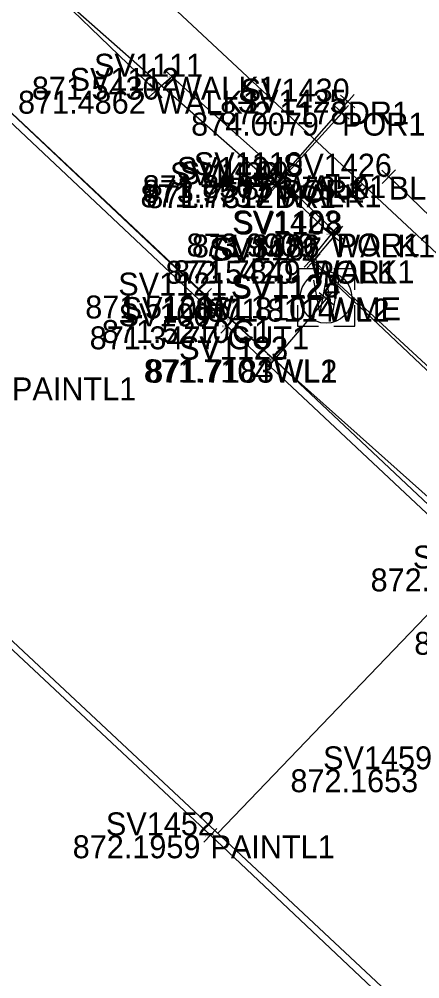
# Model space of a CAD drawing. Extents: x 1469677 to 1493262, y 375219 to 389293.
# Drawn here: x 1480076.7 to 1480097.7, y 379497.6 to 379547.9 of the extents above; entities that cross this region are included whole.
import ezdxf

# ---------------------------------------------------------------- set-up
doc = ezdxf.new("R2010")
doc.units = 0
for name, color, linetype in [('Border', 7, 'Continuous'), ('Building', 7, 'Continuous'), ('DR_X_Drive_Pipe', 7, 'Continuous'), ('DV_X_Lot_Line', 7, 'Continuous'), ('DV_X_Text', 7, 'Continuous'), ('GK_Visualization', 7, 'Continuous'), ('PNTELEV', 7, 'Continuous'), ('PNTNO', 7, 'Continuous'), ('RD_P_Text', 7, 'Continuous'), ('RW_P_Esmt_SW', 7, 'Continuous'), ('SV_X_Mon_Cells_Found', 7, 'Continuous'), ('SV_X_Text_Elevation', 7, 'Continuous'), ('Text Border', 7, 'Continuous'), ('UT_X_Water', 7, 'Continuous')]:
    doc.layers.add(name, color=color, linetype=linetype)

msp = doc.modelspace()

# ---------------------------------------------------------------- linework, layer by layer
at = {"layer": 'Border'}
msp.add_lwpolyline([(1480114.175, 379522.123), (1480096.037, 379539.648)], dxfattribs=at)
at = {"layer": 'Building'}
msp.add_lwpolyline([(1480030.312, 379558.368), (1480048.994, 379540.544), (1480068.184, 379522.458), (1480086.697, 379505.162), (1480104.247, 379488.61), (1480122.276, 379471.896), (1480139.96, 379455.601)], dxfattribs=at)
at = {"layer": 'DR_X_Drive_Pipe'}
for points in [[(1480049.152, 379568.017), (1480068.611, 379550.193), (1480086.403, 379533.424), (1480090.024, 379530.079), (1480102.295, 379519.134), (1480111.734, 379511.473), (1480120.332, 379509.136), (1480127.535, 379501.668), (1480127.911, 379496.395), (1480140.166, 379484.084), (1480149.088, 379474.708), (1480164.726, 379459.482), (1480172.622, 379452.503), (1480197.813, 379429.111)], [(1480090.047, 379530.062), (1480092.778, 379533.259)]]:
    msp.add_lwpolyline(points, dxfattribs=at)
at = {"layer": 'DV_X_Lot_Line'}
msp.add_lwpolyline([(1480215.341, 379421.047), (1480197.466, 379437.463), (1480177.803, 379455.97), (1480154.79, 379476.967), (1480132.747, 379497.48), (1480113.376, 379516.728), (1480110.754, 379519.04), (1480109.877, 379518.336), (1480091.944, 379535.267), (1480093.027, 379536.619), (1480090.219, 379539.243), (1480090.463, 379539.725), (1480084.681, 379544.882), (1480083.843, 379544.144), (1480066.818, 379560.524), (1480045.662, 379580.046)], dxfattribs=at)
at = {"layer": 'PNTELEV'}
for p, q in [((1480085.054, 379544.549), (1480084.308, 379545.215)), ((1480084.348, 379544.509), (1480085.014, 379545.255)), ((1480084.681, 379544.882), (1480084.681, 379544.882)), ((1480084.218, 379544.474), (1480083.467, 379543.814)), ((1480084.173, 379543.769), (1480083.512, 379544.519)), ((1480083.843, 379544.144), (1480083.843, 379544.144)), ((1480093.514, 379543.909), (1480094.267, 379543.25)), ((1480093.561, 379543.203), (1480094.22, 379543.956)), ((1480093.256, 379542.625), (1480093.928, 379543.365)), ((1480093.891, 379543.58), (1480093.891, 379543.58)), ((1480093.222, 379543.332), (1480093.962, 379542.659)), ((1480093.592, 379542.995), (1480093.592, 379542.995)), ((1480090.016, 379539.951), (1480090.909, 379539.5)), ((1480090.756, 379539.134), (1480090.036, 379539.829)), ((1480090.049, 379539.122), (1480090.743, 379539.841)), ((1480090.237, 379539.279), (1480090.688, 379540.172)), ((1480096.397, 379539.3), (1480095.678, 379539.995)), ((1480095.69, 379539.288), (1480096.385, 379540.007)), ((1480089.684, 379539.531), (1480090.433, 379538.869)), ((1480090.389, 379539.575), (1480089.728, 379538.825)), ((1480090.584, 379538.902), (1480089.854, 379539.585)), ((1480089.878, 379538.878), (1480090.56, 379539.608)), ((1480090.396, 379539.481), (1480090.396, 379539.481)), ((1480090.463, 379539.725), (1480090.463, 379539.725)), ((1480096.037, 379539.648), (1480096.037, 379539.648)), ((1480090.058, 379539.2), (1480090.058, 379539.2)), ((1480090.219, 379539.243), (1480090.219, 379539.243)), ((1480092.636, 379536.932), (1480093.417, 379536.307)), ((1480092.714, 379536.229), (1480093.339, 379537.009)), ((1480092.924, 379536.994), (1480093.688, 379536.349)), ((1480092.983, 379536.289), (1480093.628, 379537.053)), ((1480093.027, 379536.619), (1480093.027, 379536.619)), ((1480093.306, 379536.671), (1480093.306, 379536.671)), ((1480092.308, 379534.924), (1480091.581, 379535.61)), ((1480091.601, 379534.904), (1480092.288, 379535.631)), ((1480092.466, 379534.903), (1480091.731, 379535.581)), ((1480091.759, 379534.875), (1480092.437, 379535.609)), ((1480091.944, 379535.267), (1480091.944, 379535.267)), ((1480092.098, 379535.242), (1480092.098, 379535.242)), ((1480086.039, 379533.767), (1480086.766, 379533.081)), ((1480086.745, 379533.788), (1480086.06, 379533.06)), ((1480086.403, 379533.424), (1480086.403, 379533.424)), ((1480092.398, 379533.584), (1480093.158, 379532.935)), ((1480092.453, 379532.879), (1480093.103, 379533.64)), ((1480092.778, 379533.259), (1480092.778, 379533.259)), ((1480087.462, 379532.483), (1480088.192, 379531.799)), ((1480088.169, 379532.505), (1480087.485, 379531.776)), ((1480087.222, 379532.152), (1480087.95, 379531.467)), ((1480087.928, 379532.173), (1480087.243, 379531.445)), ((1480087.586, 379531.809), (1480087.586, 379531.809)), ((1480087.827, 379532.141), (1480087.827, 379532.141)), ((1480089.657, 379530.419), (1480090.392, 379529.74)), ((1480089.667, 379530.387), (1480090.427, 379529.737)), ((1480090.363, 379530.447), (1480089.685, 379529.712)), ((1480089.722, 379529.682), (1480090.372, 379530.442)), ((1480090.024, 379530.079), (1480090.024, 379530.079)), ((1480090.047, 379530.062), (1480090.047, 379530.062)), ((1480086.331, 379505.503), (1480087.062, 379504.82)), ((1480087.038, 379505.527), (1480086.355, 379504.796)), ((1480086.697, 379505.162), (1480086.697, 379505.162))]:
    msp.add_line(p, q, dxfattribs=at)
at = {"layer": 'PNTNO'}
msp.add_line((1480092.754, 379533.324), (1480092.754, 379533.324), dxfattribs=at)
for points in [[(1480092.354, 379534.824), (1480091.254, 379534.824), (1480091.254, 379533.724)], [(1480094.254, 379533.724), (1480094.254, 379534.824), (1480093.154, 379534.824)], [(1480092.087, 379534.224), (1480092.421, 379532.424), (1480092.754, 379534.224), (1480093.087, 379532.424), (1480093.421, 379534.224)], [(1480091.254, 379532.924), (1480091.254, 379531.824), (1480092.354, 379531.824)], [(1480093.154, 379531.824), (1480094.254, 379531.824), (1480094.254, 379532.924)]]:
    msp.add_lwpolyline(points, dxfattribs=at)
msp.add_circle((1480092.754, 379533.324), 1.35, dxfattribs=at)
at = {"layer": 'RD_P_Text'}
for points in [[(1480043.308, 379574.086), (1480051.435, 379566.534), (1480067.64, 379551.083), (1480087.827, 379532.141), (1480105.189, 379515.816), (1480105.937, 379515.205), (1480115.287, 379506.588), (1480116.588, 379505.377), (1480116.999, 379505.563), (1480121.373, 379501.34), (1480121.053, 379501.135), (1480146.64, 379476.909), (1480171.177, 379454.102), (1480173.021, 379452.229), (1480182.175, 379443.675), (1480183.379, 379442.683), (1480186.184, 379440.013), (1480186.975, 379439.363), (1480207.407, 379420.301)], [(1480042.95, 379573.802), (1480051.182, 379566.018), (1480067.383, 379550.834), (1480087.586, 379531.809), (1480105.067, 379515.41), (1480105.589, 379514.887), (1480115.079, 379506.297), (1480116.303, 379505.052), (1480118.53, 379502.967), (1480120.902, 379500.821), (1480138.714, 379483.703), (1480170.84, 379453.681), (1480172.574, 379452.083), (1480181.867, 379443.345), (1480182.839, 379442.217), (1480185.607, 379439.661), (1480186.493, 379438.955), (1480206.919, 379419.855)]]:
    msp.add_lwpolyline(points, dxfattribs=at)
at = {"layer": 'SV_X_Mon_Cells_Found'}
msp.add_line((1480087.075, 379505.277), (1481914.323, 381407.96), dxfattribs=at)
msp.add_lwpolyline([(1477206.544, 382340.781), (1479657.335, 379947.979), (1480466.338, 379191.878)], dxfattribs=at)
at = {"layer": 'SV_X_Text_Elevation'}
msp.add_line((1479636.611, 379926.284), (1480557.828, 379065.308), dxfattribs=at)
at = {"layer": 'Text Border'}
msp.add_lwpolyline([(1480073.139, 379545.812), (1480077.692, 379550.115), (1480090.058, 379539.2), (1480093.891, 379543.58)], dxfattribs=at)
at = {"layer": 'UT_X_Water'}
msp.add_lwpolyline([(1480113.669, 379522.468), (1480109.941, 379518.779), (1480092.098, 379535.242), (1480093.306, 379536.671), (1480090.396, 379539.481), (1480093.592, 379542.995)], dxfattribs=at)

# ---------------------------------------------------------------- texts
at = {"layer": 'DV_X_Text'}
for s, height, p in [('871.5430', 1.2, (1480077.341, 379543.682)), ('871.54', 0.06, (1480084.425, 379544.822)), ('871.4862', 1.2, (1480076.615, 379542.944)), ('871.49', 0.06, (1480083.586, 379544.084)), ('872.1178', 1.2, (1480087.184, 379542.38)), ('872.12', 0.06, (1480093.636, 379543.52)), ('874.0079', 1.2, (1480085.684, 379541.795)), ('874.01', 0.06, (1480093.328, 379542.935)), ('871.8503', 1.2, (1480083.141, 379538.525)), ('873.9571', 1.2, (1480083.147, 379538.281)), ('873.7859', 1.2, (1480088.346, 379538.448)), ('873.96', 0.06, (1480090.11, 379539.421)), ('871.85', 0.06, (1480090.207, 379539.665)), ('873.79', 0.06, (1480095.756, 379539.588)), ('871.7737', 1.2, (1480083.03, 379538.043)), ('871.7312', 1.2, (1480083.332, 379538)), ('871.73', 0.06, (1480089.802, 379539.14)), ('871.77', 0.06, (1480089.963, 379539.183)), ('873.9909', 1.2, (1480085.445, 379535.471)), ('871.8686', 1.2, (1480085.724, 379535.419)), ('871.87', 0.06, (1480092.771, 379536.559)), ('873.99', 0.06, (1480093.023, 379536.611)), ('872.5420', 1.2, (1480084.341, 379534.042)), ('871.7849', 1.2, (1480084.736, 379534.067)), ('871.78', 0.06, (1480091.688, 379535.207)), ('872.54', 0.06, (1480091.819, 379535.182)), ('871.5121', 1.2, (1480080.137, 379532.224)), ('871.8107', 1.2, (1480085.905, 379532.124)), ('871.51', 0.06, (1480086.169, 379533.364)), ('871.81', 0.06, (1480092.52, 379533.264)), ('871.8114', 1.2, (1480086.525, 379532.059)), ('871.81', 0.06, (1480092.544, 379533.199)), ('871.3477', 1.2, (1480080.368, 379530.609)), ('871.5210', 1.2, (1480081.006, 379530.941)), ('871.35', 0.06, (1480087.329, 379531.749)), ('871.52', 0.06, (1480087.571, 379532.081)), ('871.7104', 1.2, (1480083.204, 379528.879)), ('871.7183', 1.2, (1480083.331, 379528.862)), ('871.71', 0.06, (1480089.791, 379530.019)), ('871.72', 0.06, (1480089.792, 379530.002)), ('872.1488', 1.2, (1480095.087, 379517.934)), ('872.2076', 1.2, (1480097.375, 379514.616)), ('872.1653', 1.2, (1480090.887, 379507.419)), ('872.1959', 1.2, (1480079.479, 379503.962)), ('872.20', 0.06, (1480086.414, 379505.102))]:
    msp.add_text(s, height=height, dxfattribs=at).set_placement(p)
at = {"layer": 'GK_Visualization'}
for s, p in [('WALK1', (1480084.681, 379543.682)), ('WALK1', (1480083.843, 379542.944)), ('DR1', (1480093.891, 379542.38)), ('POR1', (1480093.592, 379541.795)), ('WALK1', (1480090.463, 379538.525)), ('POR1', (1480090.396, 379538.281)), ('BLD1', (1480096.037, 379538.448)), ('DR1', (1480090.058, 379538)), ('WALK1', (1480090.219, 379538.043)), ('WALK1', (1480093.027, 379535.419)), ('POR1', (1480093.306, 379535.471)), ('WALK1', (1480091.944, 379534.067)), ('POR1', (1480092.098, 379534.042)), ('WL1', (1480086.403, 379532.224)), ('WME', (1480092.754, 379532.124)), ('WL2', (1480092.778, 379532.059)), ('GUT1', (1480087.586, 379530.609)), ('C1', (1480087.827, 379530.941)), ('WL1', (1480090.024, 379528.879)), ('WL2', (1480090.047, 379528.862)), ('PAINTL1', (1480076.297, 379527.935)), ('PAINTL1', (1480086.697, 379503.962))]:
    msp.add_text(s, height=1.2, dxfattribs=at).set_placement(p)
at = {"layer": 'RW_P_Esmt_SW'}
for s, height, p in [('SV1111', 1.2, (1480080.599, 379544.882)), ('SV1112', 1.2, (1480079.319, 379544.144)), ('SV1111', 0.06, (1480084.477, 379544.882)), ('SV1430', 1.2, (1480088.279, 379543.58)), ('SV1112', 0.06, (1480083.617, 379544.144)), ('SV1425', 1.2, (1480088.122, 379542.995)), ('SV1430', 0.06, (1480093.61, 379543.58)), ('SV1425', 0.06, (1480093.319, 379542.995)), ('SV1110', 1.2, (1480085.825, 379539.725)), ('SV1426', 1.2, (1480090.492, 379539.648)), ('SV1429', 1.2, (1480084.579, 379539.2)), ('SV1424', 1.2, (1480084.936, 379539.481)), ('SV1109', 1.2, (1480085.09, 379539.243)), ('SV1424', 0.06, (1480090.123, 379539.481)), ('SV1110', 0.06, (1480090.231, 379539.725)), ('SV1426', 0.06, (1480095.76, 379539.648)), ('SV1429', 0.06, (1480089.784, 379539.2)), ('SV1109', 0.06, (1480089.963, 379539.243)), ('SV1423', 1.2, (1480087.836, 379536.671)), ('SV1108', 1.2, (1480087.898, 379536.619)), ('SV1422', 1.2, (1480086.638, 379535.242)), ('SV1107', 1.2, (1480086.825, 379535.267)), ('SV1108', 0.06, (1480092.771, 379536.619)), ('SV1423', 0.06, (1480093.033, 379536.671)), ('SV1107', 0.06, (1480091.688, 379535.267)), ('SV1422', 0.06, (1480091.825, 379535.242)), ('SV1121', 1.2, (1480081.866, 379533.424)), ('SV1125', 1.2, (1480087.767, 379533.324)), ('SV1124', 1.2, (1480087.8, 379533.259)), ('SV1006', 1.2, (1480082.045, 379532.141)), ('SV1121', 0.06, (1480086.176, 379533.424)), ('SV1125', 0.06, (1480092.505, 379533.324)), ('SV1124', 0.06, (1480092.529, 379533.259)), ('SV1007', 1.2, (1480081.88, 379531.809)), ('SV1007', 0.06, (1480087.301, 379531.809)), ('SV1006', 0.06, (1480087.538, 379532.141)), ('SV1122', 1.2, (1480085.046, 379530.079)), ('SV1123', 1.2, (1480085.06, 379530.062)), ('SV1122', 0.06, (1480089.775, 379530.079)), ('SV1123', 0.06, (1480089.798, 379530.062)), ('SV1129', 1.2, (1480097.298, 379519.134)), ('SV1459', 1.2, (1480092.597, 379508.619)), ('SV1452', 1.2, (1480081.218, 379505.162)), ('SV1452', 0.06, (1480086.423, 379505.162))]:
    msp.add_text(s, height=height, dxfattribs=at).set_placement(p)

doc.saveas('drawing.dxf')
